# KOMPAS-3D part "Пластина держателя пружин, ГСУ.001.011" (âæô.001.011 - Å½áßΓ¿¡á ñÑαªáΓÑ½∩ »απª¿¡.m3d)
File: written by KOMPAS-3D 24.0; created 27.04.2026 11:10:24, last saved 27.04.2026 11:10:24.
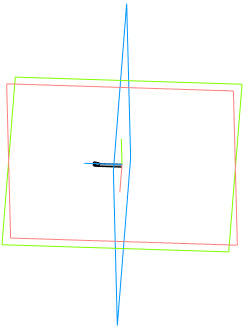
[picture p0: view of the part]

Document properties: Автор: User7; Полное имя файла: C:\Users\User7\Desktop\Двигатель мясорубки\ГСУ.001.011 - Пластина держателя пружин.m3d

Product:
- Part/product: Пластина держателя пружин  | designation ГСУ.001.011
    Масса: 0.000005

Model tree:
1. Эскиз:1
2. Листовое тело:1
     Расстояние 1 = 0.8; Толщина листового тела = 0.1
3. Сгиб(1) - Листовое тело:1
     Радиус сгиба = 0.2; Коэффициент = 0.4; Величина сгиба = 10
4. Разогнуть:1  (with: Грань.Листовое тело:1)
5. Эскиз:2  (with: Грань.Листовое тело:1, Ребро.Листовое тело:1)
6. Элемент выдавливания:1
     Расстояние 2 = 10
7. Согнуть:1  (with: Грань.Листовое тело:1)

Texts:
  ГСУ.001.011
